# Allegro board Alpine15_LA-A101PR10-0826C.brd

Outline 344.9 x 190.9 mm; copper layers: TOP, GND1, IN1, VCC, IN2, IN3, GND2, BOTTOM. Coordinates in mm from the lower left corner of the outline.

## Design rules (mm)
constraint set DEFAULT: min track width 0.102
net group CL_LINK: nets PCH_CL_RST1# PCH_CL_RST1#_R
net group CLK-15/15: nets PCH_AZ_BITCLK PCH_AZ_CODEC_BITCLK
net group CRT10\: nets VMM2310_CLK_DDC2 VMM2310_DAT_DDC2
net group DIFFPAIR6: nets MSCLK MSDATA
net group DIFFPAIR7: nets IO_USBP2+ IO_USBP2-
net group DIFFPAIR8: nets USB3RN4_D- USB3RP4_D+
net group DIFFPAIR9: nets USB3TN4_D- USB3TP4_D+
net group DIFFPAIR11: nets PS2_CLK_TS PS2_DAT_TS
net group DIFFPAIR12: nets USBP6_D+ USBP6_D-
net group DIFFPAIR22: nets SATA_PTX_DKRX_N0 SATA_PTX_DKRX_P0
net group DIFFPAIR23: nets SATA_ODD_PRX_DTX_N2_C SATA_ODD_PRX_DTX_P2_C
net group DIFFPAIR24: nets SATA_ODD_PTX_DRX_N2_C SATA_ODD_PTX_DRX_P2_C
net group DIFFPAIR25: nets PEG_EXP PEG_EXP#
net group DP1: nets EXP_PRX_EXPTX_N6_CL EXP_PRX_EXPTX_P6_CL
net group DP2: nets EXP_PRX_EXPTX_N6_M EXP_PRX_EXPTX_P6_M
net group DP4: nets PCIE_PRX_MMITX_N1 PCIE_PRX_MMITX_P1
net group DP5: nets PCIE_PRX_MMITX_N1_C PCIE_PRX_MMITX_P1_C
net group DP6: nets PCIE_PTX_MMIRX_N1 PCIE_PTX_MMIRX_P1
net group DP7: nets PCIE_PTX_MMIRX_N1_C PCIE_PTX_MMIRX_P1_C
net group DP9: nets PCIE_PTX_EXPRX_N_M PCIE_PTX_EXPRX_P_M
net group DP10: nets PEG_GTX_C_HRX_N0_M PEG_GTX_C_HRX_P0_M
net group DP11: nets PEG_HTX_GRX_N0_M PEG_HTX_GRX_P0_M
net group DP12: nets USX_SCL USX_SDA
net group DP13: nets PEG_GTX_C_HRX_N0_R PEG_GTX_C_HRX_P0_R
net group DP15: nets PCIE_PTX_EXPRX_N_C PCIE_PTX_EXPRX_P_C
net group DP16: nets EDID_CLK_LCD EDID_DATA_LCD
net group DP21: nets EXP_PTX_EXPRX_N6_CL EXP_PTX_EXPRX_P6_CL
net group DP22: nets EXP_PTX_EXPRX_N6_M EXP_PTX_EXPRX_P6_M
net group DPB_CA_DET: nets DPB_CA_DET DPB_CA_DET#
net group HUB_USBP1_R_D: nets HUB_USBP1_R_D+ HUB_USBP1_R_D-
net group HUB_USBP4+_D: nets HUB_USBP4+_D HUB_USBP4-_D
net group PCIE_PRX_EXPTX: nets PCIE_PRX_EXPTX_N PCIE_PRX_EXPTX_P
net group PCIE_PTX_EXPRX: nets PCIE_PTX_EXPRX_N PCIE_PTX_EXPRX_P
net group REM_DIODE1: nets REM_DIODE1_N REM_DIODE1_P
net group REM_DIODE3_: nets REM_DIODE3_N REM_DIODE3_P
net group REM_DIODE4: nets REM_DIODE4_N REM_DIODE4_P
net group S9.5(9.7/15.8): nets NVVDD_GND_SENSE NVVDD_SENSE
net group SENSE: nets VCCSENSE VSSSENSE
net group SIM: nets UIM_RESET UIM_VPP
net group SR_B: nets SRN_B SRP_B
net group THERMAL: nets REM_DIODE2_N REM_DIODE2_P
net group USBP4: nets USBP4+ USBP4-
net group 15: nets PCH_OPI_COMP PCH_PCIE_IREF PCH_PCIE_RCOMP PROC_OPI_RCOMP SATA_COMP SATA_IREF
net group 15/15: nets PCH_RTCRST# SRTCRST# USBRBIAS
net group ASYNC: nets BPM#0 BPM#1 DDR3_DRAMRST# DDR3_DRAMRST#_CPU H_CATERR# H_CPU_SVIDALRT# H_CPUPWRGD H_PROCHOT# H_PROCHOT#_R H_THERMTRIP# H_THERMTRIP#_R H_VCCST_PWRGD H_VCCST_PWRGD_XDP PCH_PLTRST# PECI_EC PECI_EC_R PLTRST_GPU# PLTRST_LAN# PLTRST_MMI# PLTRST_VMM2320# PROCHOT#_EC THERMATRIP2# VCCST_PWRGD VIDALERT_N VIDSCLK VIDSOUT XDP_OBS0_R XDP_OBS1_R
net group AUDIO: nets AUD_HP_NB_SENSE AUD_HP_OUT_L AUD_HP_OUT_R AUD_OUT_L AUD_OUT_R AUD_PC_BEEP AUD_SENSE_A AUD_SENSE_B BEEP PC_BEEP RING2 SLEEVE SPKR
net group BC-LINK: nets BC_CLK_ECE1117 BC_CLK_ECE5048 BC_DAT_ECE1117 BC_DAT_ECE5048 BC_INT#_ECE1117 BC_INT#_ECE5048
net group CLK: nets CLK_PCI_5048 CLK_PCI_DOCK CLK_PCI_FBIN CLK_PCI_LPDEBUG CLK_PCI_MEC CLK_PCI_TPM_TCM EC_32KHZ_ECE5048 EC_32KHZ_ECE5048_R PCH_SPI_CLK PCI_5048 PCI_CLK_LPC PCI_CLK_LPC_0 PCI_CLK_LPC_1 PCI_FBIN PCI_MEC PCI_TPM_TCM VMM_SPI_CLK
net group CLK-SRC: nets CLK_PCIE_EXP CLK_PCIE_EXP# CLK_PCIE_FMC CLK_PCIE_FMC# CLK_PCIE_LAN CLK_PCIE_LAN# CLK_PCIE_MINI2 CLK_PCIE_MINI2# CLK_PCIE_MMI CLK_PCIE_MMI# CLK_PEG_VGA CLK_PEG_VGA# PCIE_LAN PCIE_LAN# PCIE_MINI2 PCIE_MINI2# PCIE_MMI PCIE_MMI# PEG_VGA_EXP PEG_VGA_EXP#
net group CR_LOW: nets DSWODVREN INTRUDER# PCH_DPWROK PCH_INTVRMEN PCH_PCIE_WAKE# PCH_RSMRST#_Q PCH_RSMRST#_R PM_APWROK SIO_PWRBTN# SIO_RCIN# SYS_PWROK SYS_PWROK_R SYS_RESET#
net group CRT: nets BLUE_CRT BLUE_DOCK BLUE_DOCK_PI GREEN_CRT GREEN_DOCK GREEN_DOCK_PI RED_CRT RED_DOCK RED_DOCK_PI VMM2310_BLU VMM2310_GRN VMM2310_RED
net group CRT12: nets CLK_DDC2_CRT CLK_DDC2_DOCK DAT_DDC2_CRT DAT_DDC2_DOCK HSYNC_BUF HSYNC_DOCK VMM2310_HSYNC VMM2310_VSYNC VSYNC_BUF VSYNC_DOCK
net group DDR_A_DQS: nets DDR_A_DQS0 DDR_A_DQS1 DDR_A_DQS2 DDR_A_DQS3 DDR_A_DQS4 DDR_A_DQS5 DDR_A_DQS6 DDR_A_DQS7 DDR_A_DQS#0 DDR_A_DQS#1 DDR_A_DQS#2 DDR_A_DQS#3 DDR_A_DQS#4 DDR_A_DQS#5 DDR_A_DQS#6 DDR_A_DQS#7
net group DDR_B_DQS: nets DDR_B_DQS0 DDR_B_DQS1 DDR_B_DQS2 DDR_B_DQS3 DDR_B_DQS4 DDR_B_DQS5 DDR_B_DQS6 DDR_B_DQS7 DDR_B_DQS#0 DDR_B_DQS#1 DDR_B_DQS#2 DDR_B_DQS#3 DDR_B_DQS#4 DDR_B_DQS#5 DDR_B_DQS#6 DDR_B_DQS#7
net group DDRA-ADD: nets DDR_A_BS0 DDR_A_BS1 DDR_A_BS2 DDR_A_CAS# DDR_A_MA0 DDR_A_MA1 DDR_A_MA2 DDR_A_MA3 DDR_A_MA4 DDR_A_MA5 DDR_A_MA6 DDR_A_MA7 DDR_A_MA8 DDR_A_MA9 DDR_A_MA10 DDR_A_MA11 DDR_A_MA12 DDR_A_MA13 DDR_A_MA14 DDR_A_MA15 DDR_A_RAS# DDR_A_WE#
net group DDRA-CLK: nets M_CLK_DDR0 M_CLK_DDR1 M_CLK_DDR#0 M_CLK_DDR#1
net group DDRA-CTL: nets DDR_CKE0_DIMMA DDR_CKE1_DIMMA DDR_CS0_DIMMA# DDR_CS1_DIMMA# M_ODT0 M_ODT1
net group DDRA-D0: nets DDR_A_D0 DDR_A_D1 DDR_A_D2 DDR_A_D3 DDR_A_D4 DDR_A_D5 DDR_A_D6 DDR_A_D7
net group DDRA-D1: nets DDR_A_D8 DDR_A_D9 DDR_A_D10 DDR_A_D11 DDR_A_D12 DDR_A_D13 DDR_A_D14 DDR_A_D15
net group DDRA-D2: nets DDR_A_D16 DDR_A_D17 DDR_A_D18 DDR_A_D19 DDR_A_D20 DDR_A_D21 DDR_A_D22 DDR_A_D23
net group DDRA-D3: nets DDR_A_D24 DDR_A_D25 DDR_A_D26 DDR_A_D27 DDR_A_D28 DDR_A_D29 DDR_A_D30 DDR_A_D31
net group DDRA-D4: nets DDR_A_D32 DDR_A_D33 DDR_A_D34 DDR_A_D35 DDR_A_D36 DDR_A_D37 DDR_A_D38 DDR_A_D39
net group DDRA-D5: nets DDR_A_D40 DDR_A_D41 DDR_A_D42 DDR_A_D43 DDR_A_D44 DDR_A_D45 DDR_A_D46 DDR_A_D47
net group DDRA-D6: nets DDR_A_D48 DDR_A_D49 DDR_A_D50 DDR_A_D51 DDR_A_D52 DDR_A_D53 DDR_A_D54 DDR_A_D55
net group DDRA-D7: nets DDR_A_D56 DDR_A_D57 DDR_A_D58 DDR_A_D59 DDR_A_D60 DDR_A_D61 DDR_A_D62 DDR_A_D63
net group DDRB-ADD: nets DDR_B_BS0 DDR_B_BS1 DDR_B_BS2 DDR_B_CAS# DDR_B_MA0 DDR_B_MA1 DDR_B_MA2 DDR_B_MA3 DDR_B_MA4 DDR_B_MA5 DDR_B_MA6 DDR_B_MA7 DDR_B_MA8 DDR_B_MA9 DDR_B_MA10 DDR_B_MA11 DDR_B_MA12 DDR_B_MA13 DDR_B_MA14 DDR_B_MA15 DDR_B_RAS# DDR_B_WE#
net group DDRB-CLK: nets M_CLK_DDR2 M_CLK_DDR3 M_CLK_DDR#2 M_CLK_DDR#3
net group DDRB-CTL: nets DDR_CKE2_DIMMB DDR_CKE3_DIMMB DDR_CS2_DIMMB# DDR_CS3_DIMMB# M_ODT2 M_ODT3
net group DDRB-D0: nets DDR_B_D0 DDR_B_D1 DDR_B_D2 DDR_B_D3 DDR_B_D4 DDR_B_D5 DDR_B_D6 DDR_B_D7
net group DDRB-D1: nets DDR_B_D8 DDR_B_D9 DDR_B_D10 DDR_B_D11 DDR_B_D12 DDR_B_D13 DDR_B_D14 DDR_B_D15
net group DDRB-D2: nets DDR_B_D16 DDR_B_D17 DDR_B_D18 DDR_B_D19 DDR_B_D20 DDR_B_D21 DDR_B_D22 DDR_B_D23
net group DDRB-D3: nets DDR_B_D24 DDR_B_D25 DDR_B_D26 DDR_B_D27 DDR_B_D28 DDR_B_D29 DDR_B_D30 DDR_B_D31
net group DDRB-D4: nets DDR_B_D32 DDR_B_D33 DDR_B_D34 DDR_B_D35 DDR_B_D36 DDR_B_D37 DDR_B_D38 DDR_B_D39
net group DDRB-D5: nets DDR_B_D40 DDR_B_D41 DDR_B_D42 DDR_B_D43 DDR_B_D44 DDR_B_D45 DDR_B_D46 DDR_B_D47
net group DDRB-D6: nets DDR_B_D48 DDR_B_D49 DDR_B_D50 DDR_B_D51 DDR_B_D52 DDR_B_D53 DDR_B_D54 DDR_B_D55
net group DDRB-D7: nets DDR_B_D56 DDR_B_D57 DDR_B_D58 DDR_B_D59 DDR_B_D60 DDR_B_D61 DDR_B_D62 DDR_B_D63
net group DP-INTER: nets CPU_DPB_AUX CPU_DPB_AUX# CPU_DPB_AUX#_C CPU_DPB_AUX_C DDI1_LANE_N0 DDI1_LANE_N0_C DDI1_LANE_N1 DDI1_LANE_N1_C DDI1_LANE_N2 DDI1_LANE_N2_C DDI1_LANE_N3 DDI1_LANE_N3_C DDI1_LANE_P0 DDI1_LANE_P0_C DDI1_LANE_P1 DDI1_LANE_P1_C DDI1_LANE_P2 DDI1_LANE_P2_C DDI1_LANE_P3 DDI1_LANE_P3_C
net group DP-VMM: nets DPB_DOCK_AUX DPB_DOCK_AUX# DPB_DOCK_LANE_N0 DPB_DOCK_LANE_N1 DPB_DOCK_LANE_N2 DPB_DOCK_LANE_N3 DPB_DOCK_LANE_P0 DPB_DOCK_LANE_P1 DPB_DOCK_LANE_P2 DPB_DOCK_LANE_P3 DPB_LANE_N0 DPB_LANE_N0_C DPB_LANE_N1 DPB_LANE_N1_C DPB_LANE_N2 DPB_LANE_N2_C DPB_LANE_N3 DPB_LANE_N3_C DPB_LANE_P0 DPB_LANE_P0_C DPB_LANE_P1 DPB_LANE_P1_C DPB_LANE_P2 DPB_LANE_P2_C DPB_LANE_P3 DPB_LANE_P3_C DPC_CA_DET# DPC_DOCK_AUX DPC_DOCK_AUX# DPC_DOCK_LANE_N0 DPC_DOCK_LANE_N1 DPC_DOCK_LANE_N2 DPC_DOCK_LANE_N3 DPC_DOCK_LANE_P0 DPC_DOCK_LANE_P1 DPC_DOCK_LANE_P2 DPC_DOCK_LANE_P3 DPC_LANE_N0 DPC_LANE_N0_C DPC_LANE_N1 DPC_LANE_N1_C DPC_LANE_N2 DPC_LANE_N2_C DPC_LANE_N3 DPC_LANE_N3_C DPC_LANE_P0 DPC_LANE_P0_C DPC_LANE_P1 DPC_LANE_P1_C DPC_LANE_P2 DPC_LANE_P2_C DPC_LANE_P3 DPC_LANE_P3_C SW_DPB_AUX SW_DPB_AUX# SW_DPB_AUX#_C SW_DPB_AUX_C SW_DPC_AUX SW_DPC_AUX# SW_DPC_AUX#_C SW_DPC_AUX_C
net group EDP: nets EDP_CPU_AUX EDP_CPU_AUX# EDP_CPU_AUX#_C EDP_CPU_AUX_C EDP_CPU_LANE_N0 EDP_CPU_LANE_N0_C EDP_CPU_LANE_N1 EDP_CPU_LANE_N1_C EDP_CPU_LANE_P0 EDP_CPU_LANE_P0_C EDP_CPU_LANE_P1 EDP_CPU_LANE_P1_C
net group EXP: nets EXP_PRX_EXPTX_N6 EXP_PRX_EXPTX_P6 EXP_PTX_EXPRX_N6 EXP_PTX_EXPRX_P6
net group HDA: nets PCH_AZ_CODEC_RST# PCH_AZ_CODEC_SDIN0 PCH_AZ_CODEC_SDOUT PCH_AZ_CODEC_SYNC PCH_AZ_RST# PCH_AZ_SDIN0_R PCH_AZ_SDOUT PCH_AZ_SYNC
net group HDMI: nets TMDS_CLK TMDS_CLK# TMDS_N0 TMDS_N1 TMDS_N2 TMDS_P0 TMDS_P1 TMDS_P2 TMDS_RP_CLK TMDS_RP_CLK# TMDS_RP_N0 TMDS_RP_N1 TMDS_RP_N2 TMDS_RP_P0 TMDS_RP_P1 TMDS_RP_P2 TMDSB_CON_CLK TMDSB_CON_CLK# TMDSB_CON_N0 TMDSB_CON_N1 TMDSB_CON_N2 TMDSB_CON_P0 TMDSB_CON_P1 TMDSB_CON_P2
net group HUB-USB2: nets HUB_USBP1+ HUB_USBP1- HUB_USBP2+ HUB_USBP2+_D HUB_USBP2- HUB_USBP2-_D HUB_USBP3+ HUB_USBP3- HUB_USBP4+ HUB_USBP4-
net group I2C: nets CLK_TP_SIO DAT_TP_SIO I2C0_SCL I2C0_SDA I2C1_SCL_TCH_PAD I2C1_SCL_VMM I2C1_SDA_TCH_PAD I2C1_SDA_VMM N17049026 N17049030 TMDS_DDC_SCL TMDS_DDC_SCL_R TMDS_DDC_SDA TMDS_DDC_SDA_R TP_CLK TP_DATA
net group I2S: nets DAI_12MHZ# DAI_BCLK# DAI_DI DAI_DO# DAI_LRCK# I2S_BCLK I2S_DI# I2S_DO I2S_LRCLK I2S_MCLK RES_BIAS
net group LAN: nets DOCK_LOM_TRD0+ DOCK_LOM_TRD0- DOCK_LOM_TRD1+ DOCK_LOM_TRD1- DOCK_LOM_TRD2+ DOCK_LOM_TRD2- DOCK_LOM_TRD3+ DOCK_LOM_TRD3- LAN_TX0+ LAN_TX0+R LAN_TX0- LAN_TX0-R LAN_TX1+ LAN_TX1+R LAN_TX1- LAN_TX1-R LAN_TX2+ LAN_TX2+R LAN_TX2- LAN_TX2-R LAN_TX3+ LAN_TX3+R LAN_TX3- LAN_TX3-R SW_LAN_TX0+ SW_LAN_TX0- SW_LAN_TX1+ SW_LAN_TX1- SW_LAN_TX2+ SW_LAN_TX2- SW_LAN_TX3+ SW_LAN_TX3-
net group LPC: nets CLKRUN# D_CLKRUN# D_DLDRQ1# D_LAD0 D_LAD1 D_LAD2 D_LAD3 D_LFRAME# D_SERIRQ LPC_LAD0 LPC_LAD1 LPC_LAD2 LPC_LAD3 LPC_LFRAME# PCH_PLTRST#_EC
net group LVDS: nets PCH_TXCLK+ PCH_TXCLK- PCH_TXOUT0+ PCH_TXOUT0- PCH_TXOUT1+ PCH_TXOUT1- PCH_TXOUT2+ PCH_TXOUT2- PCH_TZCLK+ PCH_TZCLK- PCH_TZOUT0+ PCH_TZOUT0- PCH_TZOUT1+ PCH_TZOUT1- PCH_TZOUT2+ PCH_TZOUT2-
net group PCIE: nets PCIE_PRX_EXPTX_N_M PCIE_PRX_EXPTX_P_M PCIE_PRX_GLANTX_N3 PCIE_PRX_GLANTX_N3_C PCIE_PRX_GLANTX_P3 PCIE_PRX_GLANTX_P3_C PCIE_PRX_WLANTX_N4 PCIE_PRX_WLANTX_P4 PCIE_PTX_GLANRX_N3 PCIE_PTX_GLANRX_N3_C PCIE_PTX_GLANRX_P3 PCIE_PTX_GLANRX_P3_C PCIE_PTX_WLANRX_N4 PCIE_PTX_WLANRX_N4_C PCIE_PTX_WLANRX_P4 PCIE_PTX_WLANRX_P4_C
net group PEG: nets PEG_GTX_C_HRX_N0 PEG_GTX_C_HRX_N1 PEG_GTX_C_HRX_N2 PEG_GTX_C_HRX_N3 PEG_GTX_C_HRX_P0 PEG_GTX_C_HRX_P1 PEG_GTX_C_HRX_P2 PEG_GTX_C_HRX_P3 PEG_GTX_HRX_N0 PEG_GTX_HRX_N1 PEG_GTX_HRX_N2 PEG_GTX_HRX_N3 PEG_GTX_HRX_P0 PEG_GTX_HRX_P1 PEG_GTX_HRX_P2 PEG_GTX_HRX_P3 PEG_HTX_C_GRX_N0 PEG_HTX_C_GRX_N1 PEG_HTX_C_GRX_N2 PEG_HTX_C_GRX_N3 PEG_HTX_C_GRX_P0 PEG_HTX_C_GRX_P1 PEG_HTX_C_GRX_P2 PEG_HTX_C_GRX_P3 PEG_HTX_GRX_N0 PEG_HTX_GRX_N1 PEG_HTX_GRX_N2 PEG_HTX_GRX_N3 PEG_HTX_GRX_P0 PEG_HTX_GRX_P1 PEG_HTX_GRX_P2 PEG_HTX_GRX_P3
net group PWR: nets 1.35V_B+ +DC1_PWR_SRC +V1.05SP_B+ +VCC_PWR_SRC +VDDRP_B+ CHAGER_SRC CHG_LGATE CHG_UGATE DL_1.35V LG_3V LG_5V LG_+VDDRP N19850625 SW1 SW2 SW_1.35V SW_++VDDRP SW_+V1.05SP U2_LGATE1 U2_LGATE2 U2_PHASE1 U2_PHASE2 U2_UGATE1 U2_UGATE2 UG_3V UG_5V UG_+VDDRP
net group RCOMP: nets SM_RCOMP0 SM_RCOMP1 SM_RCOMP2
net group SATA: nets SATA_ODD_PRX_DTX_N2 SATA_ODD_PRX_DTX_P2 SATA_ODD_PTX_DRX_N2 SATA_ODD_PTX_DRX_P2 SATA_PRX_DKTX_N0 SATA_PRX_DKTX_N0_C SATA_PRX_DKTX_P0 SATA_PRX_DKTX_P0_C SATA_PRX_DTX_N1 SATA_PRX_DTX_N1_C SATA_PRX_DTX_P1 SATA_PRX_DTX_P1_C SATA_PRX_MSATATX_N3 SATA_PRX_MSATATX_N3_M SATA_PRX_MSATATX_P3 SATA_PRX_MSATATX_P3_M SATA_PTX_DKRX_N0_C SATA_PTX_DKRX_P0_C SATA_PTX_DRX_N1 SATA_PTX_DRX_N1_C SATA_PTX_DRX_P1 SATA_PTX_DRX_P1_C SATA_PTX_MSATARX_N3 SATA_PTX_MSATARX_N3_C SATA_PTX_MSATARX_N3_M SATA_PTX_MSATARX_P3 SATA_PTX_MSATARX_P3_C SATA_PTX_MSATARX_P3_M
net group SD-1: nets SD/MMCCD# SD/MMCCLK SD/MMCCLK_R SD/MMCCMD SD/MMCDAT2 SD/MMCDAT2_R SD/MMCDAT3 SD/MMCDAT3_R SDWP
net group SD-2: nets SD_RCLK+ SD_RCLK+_D SD_RCLK- SD_RCLK-_D SD_UHS2_D0N SD_UHS2_D0N_D SD_UHS2_D0P SD_UHS2_D0P_D SD_UHS2_D1N SD_UHS2_D1N_D SD_UHS2_D1P SD_UHS2_D1P_D
net group SM-BUS: nets CARD_SMBCLK CARD_SMBDAT CHARGER_SMBCLK CHARGER_SMBDAT CLK_KBD CLK_MSE CPU_DPB_CTRLCLK CPU_DPB_CTRLDAT DAT_KBD DAT_MSE DDR_XDP_SMBCLK_R1 DDR_XDP_SMBDAT_R1 DDR_XDP_WAN_SMBCLK DDR_XDP_WAN_SMBDAT DMIC0 DMIC1 DMIC_CLK0 DMIC_CLK1 DMIC_CLK_L DOCK_SMB_CLK DOCK_SMB_DAT EDID_CLK EDID_DATA GPU_SMBCLK GPU_SMBDAT LAN_SMBCLK LAN_SMBDATA MEM_SMBCLK MEM_SMBDATA PBAT_SMBCLK PBAT_SMBDAT PCH_CL_CLK1 PCH_CL_DATA1 RTD2136_SCL RTD2136_SDA SML1_SMBCLK SML1_SMBDATA UIM_CLK UIM_DATA USH_SMBCLK USH_SMBDAT VMM_DPB_CTRLCLK VMM_DPB_CTRLDAT VMM_DPC_CTRLCLK VMM_DPC_CTRLDAT VMM_MESCL VMM_MESDA WWAN_SMBCLK WWAN_SMBDAT
net group SPI: nets PCH_SPI_CS0# PCH_SPI_CS1# PCH_SPI_DIN PCH_SPI_DO PCH_SPI_DO2 PCH_SPI_DO3 SPI_CLK32 SPI_CLK64 SPI_DIN32 SPI_DIN64 SPI_DO32 SPI_DO64 SPI_PCH_CS0#_R SPI_PCH_CS1#_R SPI_PCH_DO2_32 SPI_PCH_DO2_64 SPI_PCH_DO3_32 SPI_PCH_DO3_64 TAA_CLK32 TAA_CLK64 TAA_CS0#_R TAA_CS1#_R TAA_DIN32 TAA_DIN64 TAA_DO2_32 TAA_DO2_64 TAA_DO3_32 TAA_DO3_64 TAA_DO32 TAA_DO64 VMM_SPI_CS# VMM_SPI_DIN VMM_SPI_DO
net group SPK: nets INT_SPK_L+ INT_SPK_L- INT_SPKR_L+ INT_SPKR_R-
net group USB20: nets DOCK_USBP1+ DOCK_USBP1- DOCK_USBP1_D+ DOCK_USBP1_D- DOCK_USBP2+ DOCK_USBP2- DOCK_USBP2_D+ DOCK_USBP2_D- USBP0+ USBP0- USBP1+ USBP1- USBP1_R_D+ USBP1_R_D- USBP2+ USBP2- USBP5+ USBP5- USBP5_D+ USBP5_D- USBP6+ USBP6- USBP7+ USBP7+_D USBP7- USBP7-_D
net group USB30: nets USB3RN0 USB3RN0_D- USB3RN1 USB3RN1_C USB3RN1_R USB3RN1_R_CL USB3RN1_RC USB3RN4 USB3RP0 USB3RP0_D+ USB3RP1 USB3RP1_C USB3RP1_R USB3RP1_R_CL USB3RP1_RC USB3RP4 USB3TN0 USB3TN0_C USB3TN0_D- USB3TN1 USB3TN1_C USB3TN1_RP USB3TN1_RP_C USB3TN1_RP_CL USB3TN4 USB3TP0 USB3TP0_C USB3TP0_D+ USB3TP1 USB3TP1_C USB3TP1_RP USB3TP1_RP_C USB3TP1_RP_CL USB3TP4
net group VRAM_CLK: nets CLKA0 CLKA0# CLKA1 CLKA1#
net group VRAM_CMD: nets FBA_CMD0 FBA_CMD2 FBA_CMD3 FBA_CMD4 FBA_CMD5 FBA_CMD6 FBA_CMD7 FBA_CMD8 FBA_CMD9 FBA_CMD10 FBA_CMD11 FBA_CMD12 FBA_CMD13 FBA_CMD14 FBA_CMD15 FBA_CMD16 FBA_CMD18 FBA_CMD19 FBA_CMD20 FBA_CMD21 FBA_CMD22 FBA_CMD23 FBA_CMD24 FBA_CMD25 FBA_CMD26 FBA_CMD27 FBA_CMD28 FBA_CMD29 FBA_CMD30
net group VRAM_D0: nets DQMA0 FBA_D0 FBA_D1 FBA_D2 FBA_D3 FBA_D4 FBA_D5 FBA_D6 FBA_D7
net group VRAM_D1: nets DQMA1 FBA_D8 FBA_D9 FBA_D10 FBA_D11 FBA_D12 FBA_D13 FBA_D14 FBA_D15
net group VRAM_D2: nets DQMA2 FBA_D16 FBA_D17 FBA_D18 FBA_D19 FBA_D20 FBA_D21 FBA_D22 FBA_D23
net group VRAM_D3: nets DQMA3 FBA_D24 FBA_D25 FBA_D26 FBA_D27 FBA_D28 FBA_D29 FBA_D30 FBA_D31
net group VRAM_D4: nets DQMA4 FBA_D32 FBA_D33 FBA_D34 FBA_D35 FBA_D36 FBA_D37 FBA_D38 FBA_D39
net group VRAM_D5: nets DQMA5 FBA_D40 FBA_D41 FBA_D42 FBA_D43 FBA_D44 FBA_D45 FBA_D46 FBA_D47
net group VRAM_D6: nets DQMA6 FBA_D48 FBA_D49 FBA_D50 FBA_D51 FBA_D52 FBA_D53 FBA_D54 FBA_D55
net group VRAM_D7: nets DQMA7 FBA_D56 FBA_D57 FBA_D58 FBA_D59 FBA_D60 FBA_D61 FBA_D62 FBA_D63
net group VRAM_DQS: nets QSA0 QSA1 QSA2 QSA3 QSA4 QSA5 QSA6 QSA7 QSA#0 QSA#1 QSA#2 QSA#3 QSA#4 QSA#5 QSA#6 QSA#7
net group VREF: nets +DIMM1_VREF_DQ +DIMM2_VREF_DQ +SM_VREF_CA +SM_VREF_CA_DIMM +SM_VREF_DQ0 +SM_VREF_DQ0_DIMM1 +SM_VREF_DQ1 +SM_VREF_DQ1_DIMM2 +VREFC_UV5 +VREFC_UV7 +VREFD_UV5 +VREFD_UV7
net group XTAL: nets CLK_27M_IN CLK_27M_IN_R CLK_27M_OUT XTAL24_IN XTAL24_IN_R XTAL24_OUT XTAL24M_IN XTAL24M_OUT XTAL_OUT XTALI XTALIN XTALO XTALO_R
nets with their own width: min track width 0.254; nets CLK_BIASREF N61090377
nets with their own width: min track width 0.508; nets +0.675V_P +1.2V_LDO +1.2V_LDO_AIN +1.5V_GPU +1.05V_M_JTAG +1.05V_MODPHY +1.05V_MP +1.05V_RUN +1.5V_RUNP +1.5V_THERMAL +1.05V_VCCST +1.8V_RUN_CARD +1.35V_MEM +1.35V_MEN_P +3.3V_ALW +3.3V_ALW2 +3.3V_ALW_PCH_U41 +3.3V_ALWP +3.3V_AVCC +3.3V_CAM +3.3V_HDD +3.3V_LAN +3.3V_LAN_OUT +3.3V_M +3.3V_PCIE_WWAN +3.3V_RUN +3.3V_RUN_AIN +3.3V_RUN_AUDIO +3.3V_RUN_CARD +3.3V_RUN_FFS +3.3V_RUN_TPM +3.3V_RUN_VDDA +3.3V_SUS +3.3V_TP +3.3V_USBHUB +3.3V_VTR +3.3V_VTR_ADC +5V_ALW +5V_ALW2 +5V_ALWP +5V_HDMI_DDC +5V_RUN +5V_RUN_AUDIO +ALC290_LDO_CAP +ALC3226_CPVEE +ALC3226_VREF +AUX_LDO +BATT_SUM +CAP_LDO +CHGR_DC_IN +COINCELL +DC_IN +DC_IN_SS +DCIN +DCPRRTC +DVDD_CORE +FB_PLLAVDD +GPU_CORE +NBDOCK_DC_IN_SS +P1.05V_PEX_VDD +PBATT +PBATT_IN_SS +PCH_ASATA3PLL +PCH_AUSB3PLL +PCH_DCPSUS +PCH_DCPSUS1 +PCH_DCPSUS4 +PCH_RTC_VCCSUS3_3 +PCH_VCC1P05 +PCH_VCCACLKPLL +PCH_VCCDSW +PCH_VCCDSW_R +PECI_VREF +PNVVDD +PWR_SRC +PWR_SRC_AC +RSVD_VCC3P3_1 +RTC_CELL +RTC_CELL_VBAT +SD_IO_LDO +SDC_IN +SIM_PWR +SM_VREF_CA_DIMMA +SM_VREF_CA_DIMMB +SWR_LX +SWR_V12 +V1.05S_APLLOPI +V_DDR_REF +VCC_CORE +VCCIO_OUT +VCCIOA_OUT +VCHGR +VDDA_AVDD1 +VDDA_AVDD2 +VDDRP +VLDOIN_1.35V +VR_CAP +VREFOUT EDP_COMP GND GNDA GNDA_CHG HDMI_OB PEX_PLLVDD_GPU
nets with their own width: min track width 1.016; nets +1.05V_VMM_VDD +3.3V_RUN_VDDIO +DOCK_PWR_BAR +LOM_VCT +PCH_VCCDSW3_3 +VDDA_PVDD +VHDMI_VCC
nets with their own width: min track width 1.524; nets +0.675V_DDR_VTT +1.05V_M +1.05V_VMM_VDDTX +3.3V_HDD_C +5V_HDD +5V_MOD +BL_PWR_SRC
nets with their own width: min track width 2.032; nets +0.9V_LAN +1.05V_MODPHY_PCH +1.5V_RUN +3.3V_ALW_PCH +3.3V_DVCC +3.3V_WLAN +5V_USB_CHG_PWR +LCDVDD

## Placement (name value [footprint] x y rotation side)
C3  10U_0603_6.3V6M~D  [C_0603]  159.4 104.49 90 top
C5  0.1U_0402_25V6K~D  [C_0402]  213 67.27 90 bottom
C6  0.1U_0402_25V6K~D  [C_0402]  191.23 71.16 180 bottom
C7  22U_0805_6.3V6M~D  [C_0805]  17.34 116.14 180 bottom
C8  1U_0603_10V6K~D  [C_0603]  189.5 164.18 270 top
C9  0.1U_0402_25V6K~D  [C_0402]  179.74 168.54 0 top
C10  0.01U_0402_16V7K~D  [C_0402]  188.36 164.2 270 top
C11  0.1U_0402_25V6K~D  [C_0402]  179.74 169.43 0 top
C12  0.01U_0402_16V7K~D  [C_0402]  187.47 164.2 270 top
C13  0.01U_0402_16V7K~D  [C_0402]  181.53 168.52 90 top
C14  0.01U_0402_16V7K~D  [C_0402]  180.28 165.77 0 bottom
C15  0.1U_0402_25V6K~D  [C_0402]  182.34 167.04 180 top
C16  1U_0603_10V6K~D  [C_0603]  180.04 166.92 0 bottom
C17  0.1U_0402_25V6K~D  [C_0402]  171.67 156.12 180 top
C18  0.01U_0402_16V7K~D  [C_0402]  180.28 171.61 0 top
C19  0.1U_0402_10V7K~D  [C_0402]  182.9 150.58 90 top
C20  0.1U_0402_10V7K~D  [C_0402]  183.79 150.58 90 top
C21  1U_0603_10V6K~D  [C_0603]  178.64 166.92 180 bottom
C22  0.1U_0402_25V6K~D  [C_0402]  178.4 165.77 180 bottom
C23  0.01U_0402_16V7K~D  [C_0402]  171.64 157.04 180 top
C24  0.01U_0402_16V7K~D  [C_0402]  171.67 154.98 180 top
C25  1U_0603_10V6K~D  [C_0603]  178.64 171.74 180 bottom
C26  1U_0603_10V6K~D  [C_0603]  175.97 166.92 180 bottom
C27  0.1U_0402_25V6K~D  [C_0402]  178.55 169.41 90 top
C28  0.01U_0402_16V7K~D  [C_0402]  175.73 165.77 180 bottom
C29  0.01U_0402_16V7K~D  [C_0402]  177.66 169.41 90 top
C30  4.7U_0603_6.3V6K~D  [C_0603]  155.08 107.33 180 top
C34  0.1U_0402_25V6K~D  [C_0402]  159.4 150.23 270 top
C42  18P_0402_50V8J  [C_0402]  189.3 152.18 0 top
C43  18P_0402_50V8J  [C_0402]  187.24 154.87 90 top
C50  1U_0603_10V6K~D  [C_0603]  12.64 17.98 270 bottom
C73  0.1U_0402_25V6K~D  [C_0402]  158.36 109.02 270 top
C75  0.1U_0402_25V6K~D  [C_0402]  152.7 107.53 270 top
C76  33P_0402_50V8J~D  [C_0402]  206.77 62.83 90 bottom
C85  33P_0402_50V8J~D  [C_0402]  196.03 61.51 0 bottom
C87  0.1U_0402_10V7K~D  [C_0402]  13.66 107.23 0 top
C88  10U_0805_10V6K  [C_0805]  13.74 105.84 0 top
C93  0.1U_0402_25V6K~D  [C_0402]  158.51 165.95 90 top
C94  0.1U_0402_10V7K~D  [C_0402]  160.84 156.17 270 top
C95  0.1U_0402_10V7K~D  [C_0402]  161.76 156.17 270 top
C97  0.1U_0402_25V6K~D  [C_0402]  164.48 165.7 90 top
C98  0.1U_0402_10V7K~D  [C_0402]  166.26 156.2 270 top
C99  0.1U_0402_10V7K~D  [C_0402]  167.17 156.2 270 top
C101  10U_0603_6.3V6M~D  [C_0603]  215.87 126.64 90 top
C102  0.1U_0402_25V6K~D  [C_0402]  217.39 120.94 180 top
C103  0.1U_0402_10V7K~D  [C_0402]  19.28 103.36 0 bottom
C105  0.01U_0402_16V7K~D  [C_0402]  219.89 135.63 180 top
C106  0.01U_0402_16V7K~D  [C_0402]  219.89 134.68 180 top
C108  0.01U_0402_16V7K~D  [C_0402]  219.51 131.29 180 top
C109  0.01U_0402_16V7K~D  [C_0402]  219.51 132.18 180 top
C111  1000P_0402_50V7K~D  [C_0402]  224.14 114.43 0 bottom
C112  0.1U_0402_25V6K~D  [C_0402]  224.14 115.32 0 bottom
C113  0.1U_0402_25V6K~D  [C_0402]  224.71 123.39 0 bottom
C114  0.1U_0402_25V6K~D  [C_0402]  223.84 123.38 90 bottom
C115  0.1U_0402_25V6K~D  [C_0402]  311.15 147.47 270 bottom
C116  10U_0805_10V6K  [C_0805]  317.01 152.06 180 top
C117  10U_0805_10V6K  [C_0805]  323.74 152.78 270 bottom
C118  1U_0603_10V6K~D  [C_0603]  305.2 158.72 90 bottom
C119  0.1U_0402_25V6K~D  [C_0402]  310.13 158.68 90 bottom
C120  0.1U_0402_25V6K~D  [C_0402]  306.32 158.68 90 bottom
C121  10U_0805_10V6K  [C_0805]  302.86 158.06 180 bottom
C122  10U_0805_10V6K  [C_0805]  299.86 154.85 180 bottom
C123  0.1U_0402_25V6K~D  [C_0402]  302.2 154.34 180 bottom
C124  1000P_0402_50V7K~D  [C_0402]  289.7 146.52 90 top
C125  1000P_0402_50V7K~D  [C_0402]  289.76 148.89 90 top
C126  1000P_0402_50V7K~D  [C_0402]  289.7 151.09 90 top
C127  1000P_0402_50V7K~D  [C_0402]  289.76 153.33 90 top
C128  10U_0805_10V6K  [C_0805]  274.46 171.91 180 bottom
C129  0.1U_0402_25V6K~D  [C_0402]  302.66 151.29 180 bottom
C130  22P_0402_50V8J  [C_0402]  304.61 161.07 0 bottom
C131  1U_0603_10V4Z~D  [C_0603]  314.58 146.25 90 bottom
C133  0.1U_0402_25V6K~D  [C_0402]  311.34 161.33 0 bottom
C134  2.2U_0603_6.3V6K~D  [C_0603]  302.45 148.79 270 bottom
C135  0.1U_0402_10V7K~D  [C_0402]  307.34 160.84 90 bottom
C136  10P_0402_50V8J~D  [C_0402]  308.23 160.52 90 bottom
C137  0.1U_0402_25V6K~D  [C_0402]  317.06 158.53 0 bottom
C138  2.2U_0603_6.3V6K~D  [C_0603]  305.37 146.88 180 bottom
C139  22P_0402_50V8J  [C_0402]  300.7 161.07 180 bottom
C140  10U_0805_10V6K  [C_0805]  317.31 150.21 270 bottom
C141  0.1U_0402_25V6K~D  [C_0402]  330.37 157.14 180 top
C142  0.1U_0402_25V6K~D  [C_0402]  291.18 144.82 180 bottom
C143  0.1U_0402_25V6K~D  [C_0402]  311.34 160.44 0 bottom
C144  0.1U_0402_25V6K~D  [C_0402]  299.72 150.49 90 bottom
C145  1U_0603_10V6K~D  [C_0603]  269.19 177.84 180 bottom
C147  1000P_0402_50V7K~D  [C_0402]  270.1 178.23 270 top
C148  470P_0402_50V7K~D  [C_0402]  271.38 178.23 270 top
C149  1U_0603_10V6K~D  [C_0603]  270.48 174.31 270 bottom
C150  0.1U_0402_25V6K~D  [C_0402]  302.65 150.31 180 bottom
C152  470P_0402_50V7K~D  [C_0402]  88.46 75.63 270 bottom
C153  1U_0603_10V6K~D  [C_0603]  87.08 76.81 90 bottom
C154  1U_0603_10V6K~D  [C_0603]  91.78 76.74 90 bottom
C155  0.1U_0402_10V7K~D  [C_0402]  182.01 150.58 90 top
C156  0.1U_0402_10V7K~D  [C_0402]  181.12 150.58 90 top
C157  0.1U_0402_10V7K~D  [C_0402]  180.23 150.58 90 top
C158  0.1U_0402_10V7K~D  [C_0402]  179.34 150.58 90 top
C159  0.1U_0402_10V7K~D  [C_0402]  178.41 150.6 90 top
C160  0.1U_0402_10V7K~D  [C_0402]  177.52 150.6 90 top
C161  0.1U_0402_10V7K~D  [C_0402]  176.57 150.6 90 top
C162  0.1U_0402_10V7K~D  [C_0402]  175.62 150.6 90 top
C163  470P_0402_50V7K~D  [C_0402]  89.77 75.63 270 bottom
C167  0.1U_0402_25V6K~D  [C_0402]  312.1 146.55 90 bottom
C169  2.2U_0603_10V6K  [C_0603]  313.31 147.65 270 bottom
C176  0.1U_0402_10V7K~D  [C_0402]  193.66 150.97 180 top
C177  0.1U_0402_10V7K~D  [C_0402]  198.5 141.18 270 top
C178  0.1U_0402_10V7K~D  [C_0402]  192.75 150.02 0 top
C179  0.1U_0402_10V7K~D  [C_0402]  193.66 151.86 180 top
C180  10U_0603_6.3V6M~D  [C_0603]  199.58 141.17 270 top
C181  0.1U_0402_10V7K~D  [C_0402]  192.75 149.13 0 top
C182  1U_0603_10V6K~D  [C_0603]  205.67 146.25 180 top
C183  0.1U_0402_10V7K~D  [C_0402]  193.69 152.79 180 top
C184  0.1U_0402_10V7K~D  [C_0402]  202.49 143.84 0 top
C185  0.1U_0402_10V7K~D  [C_0402]  204.2 148.15 0 top
C186  0.1U_0402_10V7K~D  [C_0402]  204.23 150.69 0 top
C188  22U_0805_6.3V6M~D  [C_0805]  207.41 144.86 90 top
C189  27P_0402_50V8J  [C_0402]  200.68 141.2 270 top
C190  27P_0402_50V8J  [C_0402]  201.59 142.96 270 top
C191  0.1U_0402_10V7K~D  [C_0402]  19.28 104.31 0 bottom
C192  0.1U_0402_25V6K~D  [C_0402]  191.53 171.23 0 bottom
C193  0.1U_0402_25V6K~D  [C_0402]  202.27 172.33 90 top
C194  0.1U_0402_25V6K~D  [C_0402]  195.49 172.5 0 bottom
C198  0.1U_0402_10V7K~D  [C_0402]  201.73 157.74 0 top
C199  0.1U_0402_10V7K~D  [C_0402]  19.24 106.59 0 bottom
C200  0.1U_0402_25V6K~D  [C_0402]  180.05 144.06 180 top
C201  4700P_0402_25V7K~D  [C_0402]  183.33 144.82 0 top
C202  2200P_0402_50V7K~D  [C_0402]  183.4 134.32 270 top
C203  2200P_0402_50V7K~D  [C_0402]  179.47 134.28 270 top
C204  0.1U_0402_25V6K~D  [C_0402]  183.33 143.93 0 top
C206  4.7U_0603_6.3V6K~D  [C_0603]  202.63 171.08 0 bottom
C207  2200P_0402_50V7K~D  [C_0402]  160.28 108.1 90 top
C209  0.1U_0402_10V7K~D  [C_0402]  19.24 107.61 0 bottom
C210  0.1U_0402_25V6K~D  [C_0402]  27.61 26.84 0 bottom
C211  4.7U_0603_6.3V6K~D  [C_0603]  15.51 28.93 270 bottom
C212  0.1U_0402_25V6K~D  [C_0402]  18.73 21.58 270 bottom
C213  4.7U_0603_6.3V6K~D  [C_0603]  14.34 24.04 270 bottom
C214  0.1U_0402_25V6K~D  [C_0402]  20.52 20.68 180 bottom
C215  0.1U_0402_25V6K~D  [C_0402]  21.34 32.55 90 bottom
C216  0.1U_0402_25V6K~D  [C_0402]  18.46 31.03 0 bottom
C217  0.1U_0402_25V6K~D  [C_0402]  27.68 28.63 270 bottom
C218  0.1U_0402_25V6K~D  [C_0402]  19.61 21.57 0 bottom
C219  0.1U_0402_25V6K~D  [C_0402]  16.57 29.71 270 bottom
C220  4.7U_0603_6.3V6K~D  [C_0603]  19.32 33.5 270 bottom
C223  4.7U_0603_6.3V6K~D  [C_0603]  30.1 27.92 180 bottom
C224  4.7U_0603_6.3V6K~D  [C_0603]  15.43 24.06 0 bottom
C225  4.7U_0603_6.3V6K~D  [C_0603]  16.38 20.62 0 bottom
C226  0.1U_0402_25V6K~D  [C_0402]  17.91 23.34 90 bottom
C227  1U_0402_6.3V6K~D  [C_0402]  16.64 27.94 270 bottom
C228  4.7U_0603_6.3V6K~D  [C_0603]  16.51 30.78 180 bottom
C229  0.1U_0402_25V6K~D  [C_0402]  18.36 29.76 180 bottom
C230  4.7U_0603_6.3V6K~D  [C_0603]  28.7 21.25 90 bottom
C231  0.1U_0402_25V6K~D  [C_0402]  27.62 21.5 90 bottom
C232  0.1U_0402_25V6K~D  [C_0402]  22.22 33.01 270 bottom
C233  0.1U_0402_25V6K~D  [C_0402]  23.11 33.01 270 bottom
C234  0.1U_0402_25V6K~D  [C_0402]  29.68 29.76 180 bottom
C235  0.1U_0402_10V7K~D  [C_0402]  23.43 20.67 90 bottom
C236  0.1U_0402_10V7K~D  [C_0402]  24.29 20.67 90 bottom
C237  0.1U_0402_10V7K~D  [C_0402]  22.54 20.67 90 bottom
C238  0.1U_0402_10V7K~D  [C_0402]  21.65 20.67 90 bottom
C239  0.1U_0402_25V6K~D  [C_0402]  32.45 50.22 270 bottom
C240  4.7U_0603_6.3V6K~D  [C_0603]  32.45 51.38 90 bottom
C241  1U_0402_6.3V6K~D  [C_0402]  16.63 22.82 180 bottom
C242  0.1U_0402_10V7K~D  [C_0402]  287.16 171.74 0 top
C243  0.1U_0402_10V7K~D  [C_0402]  287.16 172.76 0 top
C246  0.1U_0402_25V6K~D  [C_0402]  9.61 68.99 90 bottom
C247  4.7U_0603_6.3V6K~D  [C_0603]  10.99 68.8 90 bottom
C248  0.047U_0402_16V4Z~D  [C_0402]  245.13 164.93 90 bottom
C249  0.047U_0402_16V4Z~D  [C_0402]  256.18 154.29 270 bottom
C250  33P_0402_50V8J~D  [C_0402]  241.81 141.86 90 top
C251  22U_0805_6.3V6M~D  [C_0805]  233.06 159.75 90 top
C252  33P_0402_50V8J~D  [C_0402]  242.76 141.86 90 top
C253  150U_D2_6.3VY_R15M~D  [C_D2]  244.57 131.18 180 bottom
C255  5P_0402_50V8C~D  [C_0402]  30.36 26.84 180 bottom
C256  0.1U_0402_10V7K~D  [C_0402]  232.52 157.61 0 top
C257  0.1U_0402_25V6K~D  [C_0402]  320.77 184.59 0 top
C258  0.047U_0402_16V4Z~D  [C_0402]  300.42 177.12 270 bottom
C259  0.047U_0402_16V4Z~D  [C_0402]  301.31 177.12 270 bottom
C260  0.1U_0402_25V6K~D  [C_0402]  325.9 176.24 90 bottom
C261  0.1U_0402_25V6K~D  [C_0402]  325.01 176.24 90 bottom
C262  4.7U_0603_6.3V6K~D  [C_0603]  320.54 185.68 0 top
C263  1U_0402_6.3V6K~D  [C_0402]  254.54 180.18 180 top
C264  33P_0402_50V8J~D  [C_0402]  252.63 184.3 90 top
C265  33P_0402_50V8J~D  [C_0402]  257.14 184.23 90 top
C266  33P_0402_50V8J~D  [C_0402]  257.14 183.37 270 top
C267  33P_0402_50V8J~D  [C_0402]  252.63 183.43 270 top
C268  0.1U_0402_25V6K~D  [C_0402]  200.84 84.24 90 top
C269  0.1U_0402_10V7K~D  [C_0402]  19.15 100.69 0 bottom
C270  0.1U_0402_10V7K~D  [C_0402]  19.15 101.65 0 bottom
C271  0.1U_0402_10V7K~D  [C_0402]  19.15 98.15 0 bottom
C272  0.1U_0402_10V7K~D  [C_0402]  19.15 99.11 0 bottom
C273  0.1U_0402_25V6K~D  [C_0402]  32.4 57.1 270 bottom
C280  0.1U_0402_10V7K~D  [C_0402]  232.52 156.73 0 top
C288  10U_0805_10V6K  [C_0805]  23.89 70.78 90 top
C289  0.1U_0402_25V6K~D  [C_0402]  22.5 71.16 90 top
C290  47U_0805_6.3V6M  [C_0805]  17.92 85.38 0 bottom
C291  0.1U_0402_25V6K~D  [C_0402]  17.7 84.69 90 top
C292  0.1U_0402_10V7K~D  [C_0402]  22.32 79.18 0 bottom
C293  0.1U_0402_10V7K~D  [C_0402]  22.32 80.13 0 bottom
C294  0.1U_0402_10V7K~D  [C_0402]  168.22 170.17 90 top
C295  0.1U_0402_10V7K~D  [C_0402]  167.64 171.09 270 bottom
C296  0.1U_0402_10V7K~D  [C_0402]  169.14 170.17 90 top
C297  0.1U_0402_10V7K~D  [C_0402]  168.65 171.09 270 bottom
C298  0.1U_0402_10V7K~D  [C_0402]  170.15 170.17 90 top
C299  0.1U_0402_10V7K~D  [C_0402]  169.61 171.09 270 bottom
C300  0.1U_0402_10V7K~D  [C_0402]  172.55 171.15 270 bottom
C301  0.1U_0402_10V7K~D  [C_0402]  173.47 171.15 270 bottom
C302  0.1U_0402_10V7K~D  [C_0402]  166.72 171.09 270 bottom
C303  0.1U_0402_10V7K~D  [C_0402]  171.11 170.17 90 top
C304  0.1U_0402_10V7K~D  [C_0402]  170.62 171.15 270 bottom
C305  0.1U_0402_10V7K~D  [C_0402]  172.12 170.24 90 top
C306  0.1U_0402_10V7K~D  [C_0402]  171.54 171.15 270 bottom
C307  0.1U_0402_10V7K~D  [C_0402]  173.04 170.24 90 top
C308  0.1U_0402_10V7K~D  [C_0402]  174.05 170.24 90 top
C309  0.1U_0402_10V7K~D  [C_0402]  174.94 170.24 90 top
C310  0.033U_0402_16V7K~D  [C_0402]  175.91 173.44 90 bottom
C311  0.033U_0402_16V7K~D  [C_0402]  176.67 185.05 0 top
C312  0.01U_0402_16V7K~D  [C_0402]  181.61 181.34 90 top
C313  0.01U_0402_16V7K~D  [C_0402]  182.5 181.34 90 top
C314  0.01U_0402_16V7K~D  [C_0402]  182.31 185.11 270 top
C315  0.01U_0402_16V7K~D  [C_0402]  183.19 185.11 270 top
C316  1U_0402_6.3V6K~D  [C_0402]  197.81 184.6 180 top
C317  0.1U_0603_50V7K~D  [C_0603]  157.5 181.96 90 bottom
C318  0.1U_0603_50V7K~D  [C_0603]  156.23 181.96 90 bottom
C319  12P_0402_50V8J~D  [C_0402]  199.79 176.21 180 top
C328  10U_0603_6.3V6M~D  [C_0603]  182.39 131.74 0 top
C329  0.1U_0402_25V6K~D  [C_0402]  183.59 120.73 180 top
C330  0.1U_0402_25V6K~D  [C_0402]  193.06 116.06 270 top
C331  0.1U_0402_25V6K~D  [C_0402]  199.08 122.85 0 top
C332  0.1U_0402_25V6K~D  [C_0402]  183.53 127.55 90 top
C333  0.1U_0402_16V4Z~D  [C_0402]  15.59 110.27 180 top
C334  0.1U_0402_10V7K~D  [C_0402]  182.64 127.55 90 top
C336  4.7U_0603_6.3V6K~D  [C_0603]  196.61 116.43 270 top
C337  0.047U_0402_16V4Z~D  [C_0402]  201.58 123.01 0 top
C338  0.1U_0402_25V6K~D  [C_0402]  247.62 149.39 180 bottom
C339  33P_0402_50V8J~D  [C_0402]  182.67 121.62 0 top
C340  1U_0402_6.3V6K~D  [C_0402]  161.31 110.94 180 top
C342  1U_0402_6.3V6K~D  [C_0402]  160.17 114.37 180 top
C343  1U_0402_6.3V6K~D  [C_0402]  162.18 112.72 0 top
C344  1U_0402_6.3V6K~D  [C_0402]  159.33 116.22 270 top
C345  0.1U_0402_25V6K~D  [C_0402]  155.28 120.85 180 top
C346  0.1U_0402_25V6K~D  [C_0402]  174.69 122.21 0 top
C347  1U_0402_6.3V4Z~D  [C_0402]  157.83 121.96 180 top
C348  10U_0603_6.3V6M~D  [C_0603]  168.86 139.86 0 top
C349  0.1U_0402_25V6K~D  [C_0402]  168.16 115.3 270 top
C350  0.1U_0402_25V6K~D  [C_0402]  174.69 127.67 0 top
C351  0.1U_0402_25V6K~D  [C_0402]  170.96 131.79 90 top
C352  1U_0402_6.3V4Z~D  [C_0402]  174.69 123.1 0 top
C353  0.1U_0402_25V6K~D  [C_0402]  157.83 121.07 180 top
C354  0.1U_0402_25V6K~D  [C_0402]  157.7 130.47 180 top
C355  0.1U_0402_25V6K~D  [C_0402]  166.26 131.91 90 top
C356  0.1U_0402_25V6K~D  [C_0402]  155.29 119.93 180 top
C357  0.1U_0402_25V6K~D  [C_0402]  174.69 121.32 0 top
C358  2200P_0402_50V7K~D  [C_0402]  170.37 114.34 0 top
C359  2200P_0402_50V7K~D  [C_0402]  171.29 115.23 180 top
C360  0.1U_0402_25V6K~D  [C_0402]  158.14 132.28 180 top
C361  2200P_0402_50V7K~D  [C_0402]  171.52 116.62 0 top
C362  1U_0402_6.3V6K~D  [C_0402]  157.62 123.02 90 top
C363  4.7P_0402_50V8C~D  [C_0402]  175.61 129.7 180 top
C364  33P_0402_50V8K  [C_0402]  157.3 117.62 270 top
C365  33P_0402_50V8K  [C_0402]  157.3 114.07 270 top
C366  4.7U_0603_6.3V6K~D  [C_0603]  169.31 115.54 270 top
C367  0.1U_0402_25V6K~D  [C_0402]  174.56 115.61 0 top
C368  4700P_0402_25V7K~D  [C_0402]  167.15 115.3 270 top
C369  4700P_0402_25V7K~D  [C_0402]  168.48 111.91 270 top
C370  100P_0402_50V8J~D  [C_0402]  146.34 75.45 270 top
C371  0.1U_0402_25V6K~D  [C_0402]  172.48 131.79 90 top
C372  100P_0402_50V8J~D  [C_0402]  63.52 67.93 270 top
C373  100P_0402_50V8J~D  [C_0402]  171.99 112.95 0 top
C374  0.1U_0402_25V6K~D  [C_0402]  131.33 108.88 90 top
C375  0.1U_0402_25V6K~D  [C_0402]  206.72 103.03 180 top
C376  0.1U_0402_25V6K~D  [C_0402]  207.71 103.03 0 top
C377  10P_0402_50V8J~D  [C_0402]  150.56 103.04 90 top
C378  10P_0402_50V8J~D  [C_0402]  150.56 106.24 270 top
C379  10P_0402_50V8J~D  [C_0402]  145.17 103.96 270 top
C380  10P_0402_50V8J~D  [C_0402]  145.17 104.82 90 top
C382  2200P_0402_50V7K~D  [C_0402]  174.58 113.6 0 top
C383  100P_0402_50V8J~D  [C_0402]  157.88 52.54 90 bottom
C384  2200P_0402_50V7K~D  [C_0402]  184.29 134.32 270 top
C385  10U_0805_10V6K  [C_0805]  306.49 146.63 0 bottom
C386  0.1U_0402_25V6K~D  [C_0402]  167.83 138.39 270 top
C387  0.01U_0402_16V7K~D  [C_0402]  167.78 141.97 270 top
C389  1U_0603_10V6K~D  [C_0603]  169.05 103.48 90 top
C390  470P_0402_50V7K~D  [C_0402]  167.3 101.89 180 top
C391  470P_0402_50V7K~D  [C_0402]  165.5 101.89 180 top
C393  1U_0603_10V6K~D  [C_0603]  164.18 103.64 90 top
C395  47P_0402_50V8J~D  [C_0402]  155 132.61 270 top
C396  1U_0603_10V6K~D  [C_0603]  188.93 107.86 180 top
C397  470P_0402_50V7K~D  [C_0402]  188.89 108.98 180 top
C398  470P_0402_50V7K~D  [C_0402]  188.89 109.93 180 top
C399  1U_0603_10V6K~D  [C_0603]  188.88 111.07 180 top
C400  1U_0603_10V6K~D  [C_0603]  259.86 159.68 0 bottom
C401  470P_0402_50V7K~D  [C_0402]  259.73 160.82 0 bottom
C402  1000P_0402_50V7K~D  [C_0402]  259.73 161.71 0 bottom
C403  1U_0603_10V6K~D  [C_0603]  259.73 162.85 0 bottom
C404  0.1U_0402_25V6K~D  [C_0402]  207.74 150.79 180 top
C405  1U_0603_10V6K~D  [C_0603]  311.08 159.33 0 bottom
C406  0.1U_0402_10V7K~D  [C_0402]  195.51 154.62 90 top
C408  10U_0805_10V6K  [C_0805]  316.54 159.93 0 bottom
C409  470P_0402_50V7K~D  [C_0402]  261.76 155.29 90 bottom
C410  1U_0603_10V7K~D  [C_0603]  302.13 156.56 180 bottom
C412  1U_0603_10V6K~D  [C_0603]  296.74 148.15 270 bottom
C413  .47U_0402_10V6K  [C_0402]  157.19 53.43 180 top
C414  0.01U_0402_16V7K~D  [C_0402]  111.75 114.59 90 top
C422  1U_0603_10V6K~D  [C_0603]  264.3 153.58 270 bottom
C425  1U_0603_10V6K~D  [C_0603]  258.72 153.71 270 bottom
C426  1U_0603_10V6K~D  [C_0603]  215.71 181.94 0 top
C427  470P_0402_50V7K~D  [C_0402]  260.8 155.29 90 bottom
C430  1U_0603_10V6K~D  [C_0603]  101.24 141.01 0 top
C431  1U_0603_10V6K~D  [C_0603]  218.96 115.99 180 top
C432  1U_0603_10V6K~D  [C_0603]  231.73 38.39 0 top
C434  0.1U_0402_25V6K~D  [C_0402]  120.92 118.35 270 top
C435  0.1U_0402_25V6K~D  [C_0402]  124.27 122.85 0 top
C436  0.1U_0402_25V6K~D  [C_0402]  111.6 124.37 180 top
C437  22U_0603_6.3V6M~D  [C_0603]  124.22 123.99 0 top
C438  1000P_0402_50V7K~D  [C_0402]  93.49 157.85 270 bottom
C439  0.1U_0603_50V7K~D  [C_0603]  99.33 155.68 270 bottom
C440  0.1U_0402_25V6K~D  [C_0402]  84.36 156.92 90 bottom
C441  10U_0603_6.3V6M~D  [C_0603]  123.89 126.82 0 top
C442  0.1U_0402_25V6K~D  [C_0402]  123.87 125.74 0 top
C443  10U_0603_6.3V6M~D  [C_0603]  115.08 116.18 270 top
C444  0.1U_0402_25V6K~D  [C_0402]  116.22 115.94 270 top
C445  0.1U_0402_10V7K~D  [C_0402]  117.79 117.05 270 top
C446  0.1U_0402_10V7K~D  [C_0402]  118.68 117.05 270 top
C447  0.1U_0402_10V7K~D  [C_0402]  119.14 118.99 270 top
C448  0.1U_0402_10V7K~D  [C_0402]  120.03 118.99 270 top
C449  0.1U_0402_10V7K~D  [C_0402]  117.11 118.99 270 top
C450  0.1U_0402_10V7K~D  [C_0402]  116.22 118.99 270 top
C451  0.1U_0402_25V6K~D  [C_0402]  97.04 160.87 90 bottom
C452  1U_0603_10V6K~D  [C_0603]  214.27 184.19 90 top
C453  0.1U_0603_50V7K~D  [C_0603]  98.06 154.28 90 bottom
C454  0.1U_0402_25V6K~D  [C_0402]  93.49 162.04 270 bottom
C455  0.1U_0402_25V6K~D  [C_0402]  92.52 167.04 0 bottom
C456  0.1U_0402_25V6K~D  [C_0402]  102.16 126.02 0 bottom
C458  0.1U_0603_50V7K~D  [C_0603]  92.24 140.32 180 bottom
C459  0.1U_0603_50V7K~D  [C_0603]  144.59 109.86 180 top
C460  1U_0603_10V6K~D  [C_0603]  229.25 39.79 180 top
C461  1U_0603_10V6K~D  [C_0603]  103.01 141.32 90 bottom
C462  1U_0603_10V6K~D  [C_0603]  216.42 118.78 270 top
C482  0.1U_0402_10V7K~D  [C_0402]  335.22 174.79 0 top
C633  0.1U_0402_25V6K~D  [C_0402]  86.38 15.23 270 top
C634  0.1U_0402_25V6K~D  [C_0402]  96.66 13.96 270 top
C635  0.1U_0402_25V6K~D  [C_0402]  97.81 13.96 270 top
C636  0.1U_0402_25V6K~D  [C_0402]  98.7 13.96 270 top
C645  0.1U_0402_25V6K~D  [C_0402]  85.49 15.23 270 top
C647  0.1U_0402_10V7K~D  [C_0402]  90.48 14.01 90 top
C648  0.1U_0402_10V7K~D  [C_0402]  89.46 14.01 90 top
C809  220U_6.3V_M  [C_MP6VLPS220MC4R2]  18.18 88.81 270 bottom
C1001  0.1U_0402_25V6K~D  [C_0402]  340.45 175.81 180 top
C1185  0.1U_0402_16V4Z~D  [C_0402]  340.45 176.69 180 top
C1186  0.1U_0402_16V4Z~D  [C_0402]  109.41 133.77 0 top
C1187  0.1U_0402_16V4Z~D  [C_0402]  215.41 35.52 90 top
C1188  0.1U_0402_16V4Z~D  [C_0402]  315.36 166.53 270 top
C1189  0.1U_0402_16V4Z~D  [C_0402]  313.96 166.53 270 top
C2962  0.1U_0402_16V4Z~D  [C_0402]  296.31 161.28 270 top
C2963  0.01U_0402_16V7K~D  [C_0402]  295.42 161.28 270 top
C2964  10U_0805_10V6K  [C_0805]  294.11 160.82 180 top
C2965  0.1U_0402_16V4Z~D  [C_0402]  297.2 161.28 270 top
C2966  0.1U_0402_10V7K~D  [C_0402]  293.93 163.74 0 top
C2967  0.1U_0402_10V7K~D  [C_0402]  293.93 164.69 0 top
C2968  0.1U_0402_10V7K~D  [C_0402]  294.18 165.64 0 top
C2969  0.1U_0402_10V7K~D  [C_0402]  294.18 166.59 0 top
C2972  0.1U_0402_16V4Z~D  [C_0402]  301.67 169.31 90 top
C2980  0.1U_0603_50V7K~D  [C_0603]  335.72 160.09 90 top
C2987  0.01U_0402_16V7K~D  [C_0402]  190.78 167.08 0 bottom
C2988  0.01U_0402_16V7K~D  [C_0402]  186.45 172.68 90 bottom
C2989  0.1U_0402_25V6K~D  [C_0402]  190.82 169.33 0 bottom
C2990  0.1U_0402_25V6K~D  [C_0402]  187.39 165.9 0 top
C2991  0.1U_0402_25V6K~D  [C_0402]  190.78 168.03 0 bottom
C2992  0.1U_0402_25V6K~D  [C_0402]  181.88 170.27 90 bottom
C3002  10P_0402_50V8J~D  [C_0402]  147.01 108.62 0 top
C3003  0.1U_0402_10V7K~D  [C_0402]  147.01 107.73 0 top
C3004  1000P_0402_50V7K~D  [C_0402]  231.97 39.53 0 top
C3005  0.1U_0402_25V6K~D  [C_0402]  231.97 40.42 0 top
C3022  10U_0603_6.3V6M~D  [C_0603]  224.41 59.44 180 top
C3023  0.1U_0402_10V7K~D  [C_0402]  218.99 47.28 180 top
C3024  0.1U_0402_10V7K~D  [C_0402]  219.6 52.16 90 top
C3025  0.1U_0402_10V7K~D  [C_0402]  222.47 47.46 180 top
C3026  0.1U_0402_10V7K~D  [C_0402]  226.33 56.98 90 top
C3027  0.1U_0402_10V7K~D  [C_0402]  228.49 48.63 270 top
C3028  0.1U_0402_10V7K~D  [C_0402]  228.67 52.11 0 top
C3029  0.1U_0402_10V7K~D  [C_0402]  223.07 56.89 90 top
C3030  4.7U_0603_6.3V6K~D  [C_0603]  229.63 47.47 90 top
C3031  0.1U_0402_10V7K~D  [C_0402]  223.96 57.92 0 top
C3032  1U_0402_6.3V6K~D  [C_0402]  223.96 56.97 0 top
C3033  1U_0402_6.3V6K~D  [C_0402]  227.33 45.87 270 top
C3034  0.1U_0402_10V7K~D  [C_0402]  226.38 45.87 270 top
CC1  15P_0402_50V8J  [C_0402]  180.1 59.17 270 top
CC2  15P_0402_50V8J  [C_0402]  180.1 56.48 90 top
CC3  1U_0402_6.3V6K~D  [C_0402]  198.14 59.68 270 bottom
CC4  1U_0402_6.3V6K~D  [C_0402]  203.67 60.53 270 bottom
CC5  27P_0402_50V8J~D  [C_0402]  162.58 57.52 270 top
CC6  15P_0402_50V8J  [C_0402]  151.23 92.32 180 top
CC7  15P_0402_50V8J  [C_0402]  148.54 92.32 0 top
CC8  0.1U_0402_25V6K~D  [C_0402]  181.75 77.56 90 bottom
CC9  0.1U_0402_25V6K~D  [C_0402]  195.12 56.43 90 top
CC10  0.1U_0402_25V6K~D  [C_0402]  86.58 48.93 180 top
CC11  0.1U_0402_25V6K~D  [C_0402]  101.14 46.64 0 top
CC12  2.2U_0402_6.3V6M~D  [C_0402]  149.11 59.22 270 top
CC13  2.2U_0402_6.3V6M~D  [C_0402]  138.57 57.82 180 top
CC14  12P_0402_50V8J~D  [C_0402]  168.16 59.3 270 top
CC15  12P_0402_50V8J~D  [C_0402]  169.05 58.38 90 top
CC16  10U_0603_6.3V6M~D  [C_0603]  141.81 56.43 180 top
CC17  10U_0603_6.3V6M~D  [C_0603]  145.3 57.82 90 top
CC18  10U_0603_6.3V6M~D  [C_0603]  138.83 56.68 180 top
CC19  10U_0603_6.3V6M~D  [C_0603]  145.37 56.55 180 top
CC20  10U_0603_6.3V6M~D  [C_0603]  141.81 57.7 180 top
CC21  10U_0603_6.3V6M~D  [C_0603]  145.43 55.28 180 top
CC22  0.1U_0402_25V6K~D  [C_0402]  203.88 59.33 180 top
CC23  0.1U_0402_25V6K~D  [C_0402]  203.93 53.89 180 top
CC24  0.1U_0402_25V6K~D  [C_0402]  188.06 56.38 0 top
CC25  12P_0402_50V8J~D  [C_0402]  213.95 55.03 180 top
CC26  1U_0402_6.3V6K  [C_0402]  153.05 70.99 270 top
CC27  1U_0402_6.3V6K~D  [C_0402]  161.05 77.15 270 top
CC28  22U_0603_6.3V6M~D  [C_0603]  160.75 73.24 180 top
CC29  1U_0402_6.3V6K~D  [C_0402]  162.21 78.66 180 top
CC30  1U_0402_6.3V6K~D  [C_0402]  159.66 57.39 270 top
CC31  1U_0402_6.3V6K~D  [C_0402]  163.15 77.78 270 top
CC32  1U_0402_6.3V6K~D  [C_0402]  192.22 65.95 0 top
CC33  1U_0402_6.3V6K~D  [C_0402]  160.35 79.05 270 top
CC34  10U_0603_6.3V6M~D  [C_0603]  158.26 72.56 90 top
CC35  1U_0402_6.3V6K~D  [C_0402]  165.71 56.55 0 top
CC36  0.1U_0402_10V7K~D  [C_0402]  163.12 70.25 180 top
CC37  1U_0402_6.3V6K~D  [C_0402]  163.1 71.51 180 top
CC38  0.1U_0402_10V7K~D  [C_0402]  165.71 57.44 0 top
CC39  0.1U_0402_10V7K~D  [C_0402]  162.78 69.38 180 top
CC40  0.1U_0402_10V7K~D  [C_0402]  162.59 73.59 180 top
CC41  0.1U_0402_25V6K~D  [C_0402]  97.69 73.63 270 bottom
CC42  22U_0603_6.3V6M~D  [C_0603]  155.21 101.65 90 top
CC43  22U_0603_6.3V6M~D  [C_0603]  160.75 74.44 180 top
CC44  0.1U_0402_10V7K~D  [C_0402]  159.53 69.63 90 top
CC45  1U_0402_6.3V6K~D  [C_0402]  160.11 75.53 180 top
CC46  1U_0402_6.3V6K~D  [C_0402]  161.31 71.24 270 top
CC47  22U_0805_6.3V6M~D  [C_0805]  152.29 72.81 180 top
CC48  0.1U_0402_25V6K~D  [C_0402]  101.14 48.43 0 top
CC49  22U_0603_6.3V6M~D  [C_0603]  164.86 91.35 0 top
CC50  22U_0603_6.3V6M~D  [C_0603]  152.07 70.93 180 top
CC51  1U_0402_6.3V6K~D  [C_0402]  156.74 78.38 270 top
CC52  2.2U_0402_6.3V6M~D  [C_0402]  140.22 58.84 180 top
CC53  1U_0402_6.3V6K~D  [C_0402]  162.59 72.7 180 top
CC54  1U_0402_6.3V6K~D  [C_0402]  172.44 72.45 270 top
CC55  100U_1206_6.3V6M  [C_1206]  157.37 96.68 90 top
CC56  1U_0402_6.3V6K~D  [C_0402]  156.72 73.6 270 top
CC57  12P_0402_50V8J~D  [C_0402]  213.95 55.9 180 top
CC58  1U_0402_6.3V6K~D  [C_0402]  157.88 91.22 90 top
CC59  0.1U_0402_10V7K~D  [C_0402]  159.54 77.35 270 top
CC60  1U_0402_6.3V6K~D  [C_0402]  158.18 71.61 0 top
CC61  1U_0402_6.3V6K~D  [C_0402]  167.4 96.35 90 top
CC62  10U_0603_6.3V6M~D  [C_0603]  172.86 101.89 90 top
CC63  1U_0402_6.3V6K~D  [C_0402]  157.62 78.38 270 top
CC64  1U_0402_6.3V6K~D  [C_0402]  155.46 75.98 270 top
CC65  1U_0402_6.3V6K~D  [C_0402]  158.13 54.57 90 top
CC66  1U_0402_6.3V6K~D  [C_0402]  160.42 70.12 90 top
CC67  0.022U_0402_16V7K~D  [C_0402]  102.78 13.98 270 top
CC68  0.01U_0402_16V7K~D  [C_0402]  101.16 56.81 0 top
CC69  0.022U_0402_16V7K~D  [C_0402]  155.61 25.85 270 top
CC70  0.022U_0402_16V7K~D  [C_0402]  80.99 24.55 180 bottom
CC71  330U_D3_2.5VY_R6M  [C_D2]  188.23 81.57 0 bottom
CC73  330U_D3_2.5VY_R6M  [C_D2]  100.83 66.08 270 bottom
CC74  1U_0402_6.3V6K~D  [C_0402]  168.11 80.69 180 top
CC75  100U_1206_6.3V6M  [C_1206]  168.8 99.22 90 top
CC76  22U_0603_6.3V6M~D  [C_0603]  156.29 100.75 0 top
CC77  22U_0603_6.3V6M~D  [C_0603]  155.16 104.11 90 top
CC78  100U_1206_6.3V6M  [C_1206]  159.17 93.76 180 top
CC79  100U_1206_6.3V6M  [C_1206]  163.17 93.76 180 top
CC80  12P_0402_50V8J~D  [C_0402]  203.01 55.79 0 top
CC81  2.2U_0402_6.3V6M~D  [C_0402]  136.8 59.22 0 top
CC82  0.1U_0402_25V6K~D  [C_0402]  191.58 62.01 0 top
CC84  27P_0402_50V8J~D  [C_0402]  181.93 133.41 90 top
CC85  18P_0402_50V8J~D  [C_0402]  225.49 45.87 270 top
CC86  18P_0402_50V8J~D  [C_0402]  222.65 45.66 180 top
CD1  2.2U_0402_6.3V6M~D  [C_0402]  80.99 28.36 180 bottom
CD2  0.1U_0402_25V6K~D  [C_0402]  80.99 27.47 180 bottom
CD3  0.1U_0402_25V6K~D  [C_0402]  104.79 13.96 270 top
CD4  1U_0402_6.3V6K~D  [C_0402]  112.28 27.16 270 top
CD5  1U_0402_6.3V6K~D  [C_0402]  127.78 27.16 270 top
CD6  1U_0402_6.3V6K~D  [C_0402]  127.67 17.76 90 top
CD7  1U_0402_6.3V6K~D  [C_0402]  122.44 27.16 270 top
CD8  1U_0402_6.3V6K~D  [C_0402]  112.57 17.79 90 top
CD9  1U_0402_6.3V6K~D  [C_0402]  116.86 17.74 90 top
CD10  1U_0402_6.3V6K~D  [C_0402]  116.6 27.04 270 top
CD11  1U_0402_6.3V6K~D  [C_0402]  123.6 17.76 90 top
CD12  2.2U_0402_6.3V6M~D  [C_0402]  128.49 15.15 180 bottom
CD13  0.1U_0402_25V6K~D  [C_0402]  128.49 14.26 180 bottom
CD14  10U_0603_6.3V6M~D  [C_0603]  115.59 17.25 90 top
CD15  10U_0603_6.3V6M~D  [C_0603]  119.65 17.5 90 top
CD16  10U_0603_6.3V6M~D  [C_0603]  113.68 27.53 270 top
CD17  10U_0603_6.3V6M~D  [C_0603]  117.75 27.41 270 top
CD18  10U_0603_6.3V6M~D  [C_0603]  120.92 27.28 270 top
CD19  10U_0603_6.3V6M~D  [C_0603]  126.51 17.5 90 top
CD20  10U_0603_6.3V6M~D  [C_0603]  120.94 17.52 90 top
CD21  10U_0603_6.3V6M~D  [C_0603]  125.64 27.43 270 top
CD22  330U_D3_2.5VY_R6M  [C_D3]  129.54 33.21 0 top
CD23  0.1U_0402_25V6K~D  [C_0402]  228.11 29.2 270 top
CD24  0.1U_0402_25V6K~D  [C_0402]  149.51 25.7 90 top
CD25  2.2U_0402_6.3V6M~D  [C_0402]  148.62 25.7 90 top
CD26  0.1U_0402_25V6K~D  [C_0402]  152.13 24.51 180 top
CD27  0.1U_0402_25V6K~D  [C_0402]  151.37 25.52 180 top
CD28  0.1U_0402_25V6K~D  [C_0402]  150.79 20.89 180 top
CD29  0.1U_0402_25V6K~D  [C_0402]  150.79 20 180 top
CD30  10U_0603_6.3V6M~D  [C_0603]  150.59 26.48 90 top
CD31  10U_0603_6.3V6M~D  [C_0603]  151.08 18.45 180 top
CD32  2.2U_0402_6.3V6M~D  [C_0402]  161.78 26.48 180 top
CD33  0.1U_0402_25V6K~D  [C_0402]  161.78 27.36 180 top
CD34  0.1U_0402_25V6K~D  [C_0402]  172.36 17.82 90 top
CD35  1U_0402_6.3V6K~D  [C_0402]  198.03 17.76 90 top
CD36  1U_0402_6.3V6K~D  [C_0402]  201.71 17.76 90 top
CD37  1U_0402_6.3V6K~D  [C_0402]  196.87 27.04 270 top
CD38  1U_0402_6.3V6K~D  [C_0402]  201.2 26.93 270 top
CD39  1U_0402_6.3V6K~D  [C_0402]  190.91 17.25 90 top
CD40  1U_0402_6.3V6K~D  [C_0402]  190.66 26.93 270 top
CD41  1U_0402_6.3V6K~D  [C_0402]  186.98 26.93 270 top
CD42  1U_0402_6.3V6K~D  [C_0402]  187.25 17.28 90 top
CD43  2.2U_0402_6.3V6M~D  [C_0402]  203.99 17.76 90 top
CD44  0.1U_0402_25V6K~D  [C_0402]  203.11 17.76 90 top
CD45  10U_0603_6.3V6M~D  [C_0603]  194.6 17.01 90 top
CD46  10U_0603_6.3V6M~D  [C_0603]  192.44 17.01 90 top
CD47  10U_0603_6.3V6M~D  [C_0603]  189.01 17.01 90 top
CD48  10U_0603_6.3V6M~D  [C_0603]  195.1 27.17 270 top
CD49  10U_0603_6.3V6M~D  [C_0603]  199.55 27.05 270 top
CD50  10U_0603_6.3V6M~D  [C_0603]  199.8 17.52 90 top
CD51  10U_0603_6.3V6M~D  [C_0603]  188.75 27.17 270 top
CD52  10U_0603_6.3V6M~D  [C_0603]  192.31 27.17 270 top
CD53  330U_D3_2.5VY_R6M  [C_D3]  197.85 31.24 0 top
CD54  0.1U_0402_25V6K~D  [C_0402]  226.51 24.17 0 top
CD55  0.1U_0402_25V6K~D  [C_0402]  226.51 25.06 0 top
CD56  0.1U_0402_25V6K~D  [C_0402]  225.82 18.91 270 top
CD57  0.1U_0402_25V6K~D  [C_0402]  224.93 18.91 270 top
CD58  10U_0603_6.3V6M~D  [C_0603]  226.97 19.15 270 top
CD59  10U_0603_6.3V6M~D  [C_0603]  226.39 26.2 0 top
CD60  0.1U_0402_25V6K~D  [C_0402]  226.33 27.77 90 top
CD61  2.2U_0402_6.3V6M~D  [C_0402]  227.22 27.77 90 top
CE7  4.7U_0805_25V6K~D  [C_0805]  154.58 181.56 90 bottom
CE8  4.7P_0402_50V8C~D  [C_0402]  188.61 177.05 270 top
CE9  4.7P_0402_50V8C~D  [C_0402]  185.99 176.14 90 top
CE10  100P_0402_50V8J~D  [C_0402]  107.2 157.21 270 top
CE11  100P_0402_50V8J~D  [C_0402]  107.2 158.71 90 top
CE14  0.1U_0402_25V6K~D  [C_0402]  76.67 25.18 180 bottom
CE20  0.1U_0402_25V6K~D  [C_0402]  76.67 24.29 180 bottom
CE22  0.1U_0402_25V6K~D  [C_0402]  76.67 26.07 180 bottom
CMOS1  SHORT PADS~D  [SHORTPADS]  204.74 59.6 270 bottom
CS1  0.01U_0402_16V7K~D  [C_0402]  232.77 23.57 0 top
CS2  0.01U_0402_16V7K~D  [C_0402]  232.77 24.52 0 top
CS3  0.01U_0402_16V7K~D  [C_0402]  232.78 27.44 0 top
CS4  0.01U_0402_16V7K~D  [C_0402]  232.78 28.33 0 top
CU16  0.1U_0402_10V7K~D  [C_0402]  154.19 94.6 270 top
CU17  0.1U_0402_10V7K~D  [C_0402]  155.08 94.6 270 top
CU18  0.1U_0402_10V7K~D  [C_0402]  152.42 92.06 270 top
CU19  0.1U_0402_10V7K~D  [C_0402]  153.31 92.06 270 top
CU20  0.1U_0402_10V7K~D  [C_0402]  148.23 99.48 0 top
CU21  0.1U_0402_10V7K~D  [C_0402]  148.23 100.37 0 top
CU22  0.1U_0402_10V7K~D  [C_0402]  148.23 98.59 0 top
CU23  0.1U_0402_10V7K~D  [C_0402]  148.23 97.7 0 top
CV86  10U_0603_6.3V6M  [C_0603]  48.98 84.11 180 bottom
CV87  0.1U_0402_10V7K~D  [C_0402]  96.71 77.71 270 bottom
CV88  1U_0402_6.3V6K  [C_0402]  61.6 94.26 270 top
CV89  1U_0402_6.3V6K  [C_0402]  58.25 94.25 180 top
CV90  10U_0603_6.3V6M  [C_0603]  48.98 82.84 180 bottom
CV91  10U_0603_6.3V6M  [C_0603]  54.97 91.58 0 top
CV94  1U_0402_6.3V6K  [C_0402]  55.65 94.25 180 top
CV95  1U_0402_6.3V6K  [C_0402]  52.64 92.66 0 top
CV96  10U_0603_6.3V6M  [C_0603]  57.8 92.11 0 top
CV97  1U_0402_6.3V6K  [C_0402]  59.19 94.35 270 top
CV100  1U_0402_6.3V6K  [C_0402]  54.42 97.99 0 top
CV101  1U_0402_6.3V6K  [C_0402]  54.83 102.88 180 top
CV102  10U_0603_6.3V6M  [C_0603]  57.3 108.55 90 top
CV103  1U_0402_6.3V6K  [C_0402]  61.36 105.23 180 top
CV104  15P_0402_50V8J  [C_0402]  64.54 111.27 180 top
CV105  15P_0402_50V8J  [C_0402]  65.4 111.27 0 top
CV226  0.1U_0402_10V7K~D  [C_0402]  64.66 94.45 90 top
CV227  0.1U_0402_10V7K~D  [C_0402]  60.59 94.26 270 top
CV228  0.1U_0402_10V7K~D  [C_0402]  54.42 99.58 0 top
CV231  0.1U_0402_10V7K~D  [C_0402]  56 105.23 0 top
CV232  0.1U_0402_10V7K~D  [C_0402]  49.94 116.8 90 bottom
CV233  0.1U_0402_10V7K~D  [C_0402]  63.57 104.67 270 top
CV234  0.1U_0402_10V7K~D  [C_0402]  64.72 104.67 270 top
CV235  0.1U_0402_10V7K~D  [C_0402]  62.24 104.67 270 top
CV236  0.1U_0402_10V7K~D  [C_0402]  66.68 102.11 90 top
CV239  0.1U_0402_10V7K~D  [C_0402]  65.81 100.06 270 top
CV240  0.1U_0402_10V7K~D  [C_0402]  66.7 100.06 270 top
CV2401  0.1U_0402_10V7K~D  [C_0402]  65.36 83.58 180 top
CV2402  0.1U_0402_10V7K~D  [C_0402]  71.21 93.64 180 top
CV2403  0.1U_0402_10V7K~D  [C_0402]  71.21 92.75 180 top
CV2404  0.1U_0402_10V7K~D  [C_0402]  68.29 88.66 180 top
